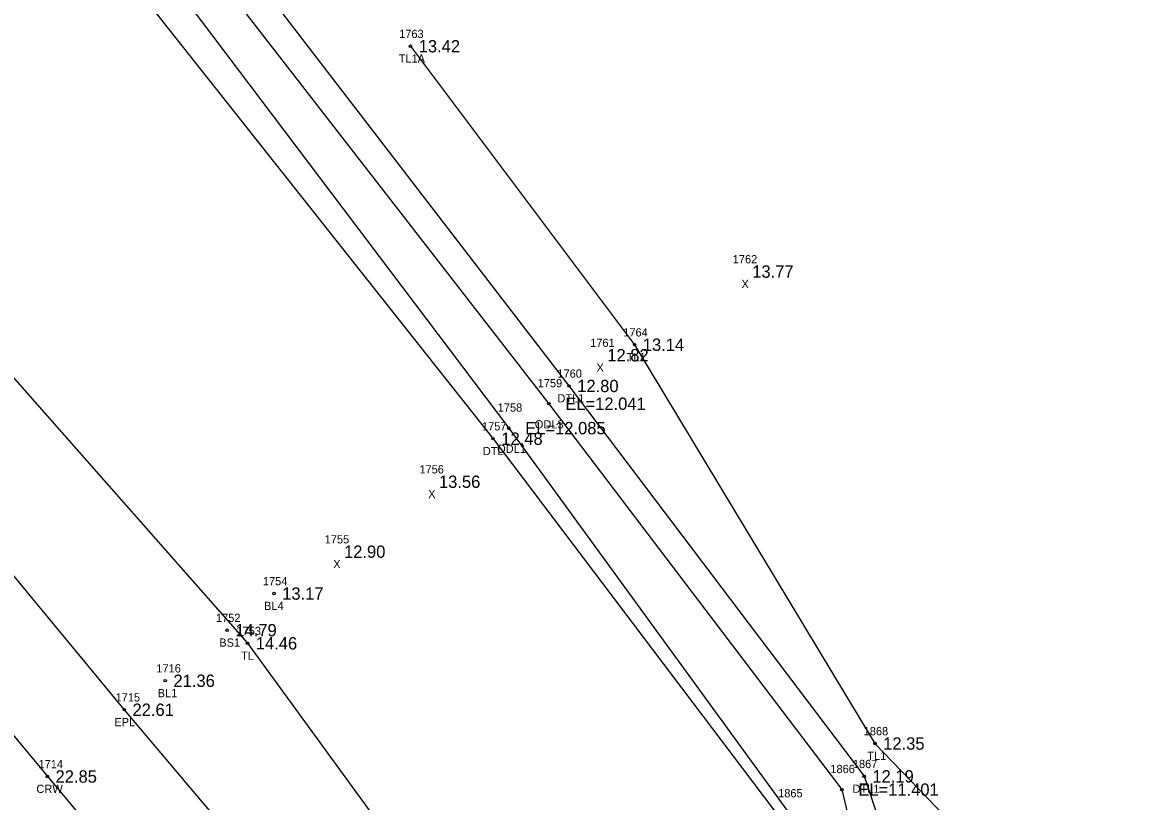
# Model space of a CAD drawing. Extents: x 2042117 to 2045853, y 303080 to 309569.
# Drawn here: x 2043937.2 to 2044074.2, y 305334.8 to 305429.3 of the extents above; entities that cross this region are included whole.
import ezdxf

# ---------------------------------------------------------------- set-up
doc = ezdxf.new("R2010")
doc.units = 0
for name, color, linetype in [('RD_DTM_BkLn_txCode', 7, 'Continuous'), ('RD_EX_H2O', 7, 'Continuous'), ('RD_EX_H2O_txCode', 7, 'Continuous'), ('RD_EX_Misc_txCode', 7, 'Continuous'), ('RD_EX_Road', 7, 'Continuous'), ('RD_EX_Road_txCode', 7, 'Continuous'), ('RD_EX_TX_H2O_ELEV', 7, 'Continuous'), ('RD_EX_TX_Misc_ELEV', 7, 'Continuous'), ('RD_EX_TX_Road_ELEV', 7, 'Continuous'), ('RD_EX_TX_VEG_ELEV', 7, 'Continuous'), ('RD_EX_VEG', 7, 'Continuous'), ('RD_EX_VEG_txCode', 7, 'Continuous'), ('RD_HC_Cl', 7, 'Continuous'), ('RD_HC_Survey_ELEV', 7, 'Continuous'), ('RD_HC_Survey_txCode', 7, 'Continuous'), ('RD_SMD_Locator', 7, 'Continuous')]:
    doc.layers.add(name, color=color, linetype=linetype)

msp = doc.modelspace()

# ---------------------------------------------------------------- linework, layer by layer
at = {"layer": 'RD_EX_H2O'}
for points in [[(2043695.41, 305785.95), (2043753.23, 305702.74), (2043816.84, 305621.67), (2043878.98, 305542.47), (2043936.42, 305466.41), (2044001.08, 305383.06), (2044036.64, 305336.24), (2044042.32, 305312.25), (2044044.08, 305296.68), (2044037.04, 305284.58), (2044037.23, 305281.89), (2044040.11, 305279.62), (2044044.74, 305276.06), (2044050.89, 305261.28), (2044092.5, 305206.78), (2044153.45, 305129.2), (2044155.72, 305128.46), (2044158.75, 305129.8), (2044171.64, 305145.93), (2044183.17, 305157.87), (2044199.16, 305188.17), (2044208.66, 305215.31)], [(2043691.65, 305782.08), (2043750.76, 305701.1), (2043812.59, 305619.17), (2043875.5, 305539.19), (2043933.11, 305463.61), (2043996.22, 305380.1), (2044030.28, 305333.3), (2044036.73, 305312.37), (2044037.31, 305297.73), (2044030.81, 305285.38), (2044029.9, 305283.95), (2044027.87, 305283.16)], [(2043688.94, 305780.02), (2043748.1, 305697.94), (2043809.2, 305616.91), (2043872.33, 305536.25), (2043929.28, 305460.89), (2043994.32, 305378.82), (2044029.48, 305332.31), (2044031.68, 305311), (2044031.99, 305298.04), (2044028.8, 305286.25)], [(2043939.38, 305468.62), (2044003.53, 305385.22), (2044039.35, 305337.85), (2044047.71, 305312.67), (2044046.57, 305295.78), (2044040.04, 305284.22), (2044040.55, 305281.91), (2044045.48, 305279.05), (2044047.12, 305275.75), (2044052.64, 305262.28), (2044093.07, 305207.37)]]:
    msp.add_lwpolyline(points, dxfattribs=at)
at = {"layer": 'RD_EX_Road'}
msp.add_lwpolyline([(2043821.87, 305499.1), (2043885.81, 305423.07), (2043949.56, 305345.93), (2044013.41, 305270.34), (2044077.97, 305194.15), (2044141.4, 305117.67), (2044205.92, 305040.83), (2044269.54, 304964.65), (2044331.73, 304891.04), (2044335.22, 304889.2), (2044346.01, 304875.31), (2044356.18, 304867.61), (2044370.01, 304868.14), (2044386.83, 304866.36), (2044389.44, 304849.53), (2044390.71, 304830.73), (2044393.77, 304818.44), (2044395.5, 304814.18), (2044398.16, 304811.09)], dxfattribs=at)
at = {"layer": 'RD_EX_VEG'}
for points in [[(2043547.51, 305881.5), (2043539.7, 305861.32), (2043541.74, 305855.07), (2043567.73, 305828.7), (2043642.4, 305738.29), (2043706.88, 305661.84), (2043768.33, 305586.86), (2043834.29, 305506.38), (2043895.63, 305432.16), (2043964.52, 305353.99), (2044012.41, 305288.23), (2044020.96, 305286.08), (2044026.64, 305287.13), (2044039.88, 305282.36)], [(2043984.29, 305426.44), (2044011.49, 305390.22), (2044040.66, 305341.83), (2044056.64, 305325.24), (2044053.79, 305304.43), (2044049.07, 305293.73), (2044039.88, 305282.36)]]:
    msp.add_lwpolyline(points, dxfattribs=at)
at = {"layer": 'RD_HC_Cl'}
msp.add_line((2043284.3, 306123.24), (2045221.31, 303804), dxfattribs=at)
at = {"layer": 'RD_SMD_Locator'}
for centre in [(2043984.29, 305426.44), (2044011.49, 305390.22), (2044003.53, 305385.22), (2044001.08, 305383.06), (2043994.32, 305378.82), (2043996.22, 305380.1), (2043967.73, 305360.03), (2043962.04, 305355.58), (2043964.52, 305353.99), (2043954.53, 305349.45), (2043949.56, 305345.93), (2044040.66, 305341.83), (2043940.22, 305337.83), (2044039.35, 305337.85), (2044036.64, 305336.24)]:
    msp.add_circle(centre, 0.15, dxfattribs=at)

# ---------------------------------------------------------------- texts
at = {"layer": 'RD_DTM_BkLn_txCode'}
for s, p in [('1754', (2043966.38, 305361.03)), ('BL4', (2043966.52, 305358.03)), ('1752', (2043960.69, 305356.58)), ('BS1', (2043961.09, 305353.58)), ('1716', (2043953.45, 305350.45)), ('BL1', (2043953.61, 305347.45))]:
    msp.add_text(s, height=1, dxfattribs=at).set_placement(p)
at = {"layer": 'RD_EX_H2O_txCode'}
for s, p in [('1760', (2044002.12, 305386.22)), ('1759', (2043999.73, 305385.06)), ('1758', (2043994.88, 305382.1)), ('DTL1', (2044002.12, 305383.22)), ('1757', (2043992.97, 305379.82)), ('ODL3', (2043999.38, 305380.06)), ('DTL', (2043993.07, 305376.82)), ('ODL1', (2043994.81, 305377.1)), ('1866', (2044035.25, 305338.24)), ('1867', (2044037.98, 305338.85)), ('DTL1', (2044037.94, 305335.85)), ('1865', (2044028.91, 305335.3))]:
    msp.add_text(s, height=1, dxfattribs=at).set_placement(p)
at = {"layer": 'RD_EX_Misc_txCode'}
for s, p in [('1762', (2044023.4, 305400.1)), ('X', (2044024.46, 305397.1)), ('1761', (2044006.1, 305389.95)), ('X', (2044006.87, 305386.95)), ('1756', (2043985.38, 305374.6)), ('X', (2043986.44, 305371.6)), ('1755', (2043973.88, 305366.11)), ('X', (2043974.92, 305363.11))]:
    msp.add_text(s, height=1, dxfattribs=at).set_placement(p)
at = {"layer": 'RD_EX_Road_txCode'}
for s, p in [('1715', (2043948.5, 305346.93)), ('EPL', (2043948.35, 305343.93))]:
    msp.add_text(s, height=1, dxfattribs=at).set_placement(p)
at = {"layer": 'RD_EX_TX_H2O_ELEV'}
for s, p in [('12.80', (2044004.53, 305384.47)), ('EL=12.041', (2044003.08, 305382.31)), ('EL=12.085', (2043998.22, 305379.35)), ('12.48', (2043995.32, 305378.07)), ('12.19', (2044040.35, 305337.1)), ('EL=11.401', (2044038.64, 305335.49))]:
    msp.add_text(s, height=1.5, dxfattribs=at).set_placement(p)
at = {"layer": 'RD_EX_TX_Misc_ELEV'}
for s, p in [('13.77', (2044025.77, 305398.35)), ('12.82', (2044008.18, 305388.2)), ('13.56', (2043987.75, 305372.85)), ('12.90', (2043976.23, 305364.36)), ('13.17', (2043968.73, 305359.28)), ('14.79', (2043963.04, 305354.83)), ('21.36', (2043955.53, 305348.7))]:
    msp.add_text(s, height=1.5, dxfattribs=at).set_placement(p)
at = {"layer": 'RD_EX_TX_Road_ELEV'}
msp.add_text('22.61', height=1.5, dxfattribs=at).set_placement((2043950.56, 305345.18))
at = {"layer": 'RD_EX_TX_VEG_ELEV'}
for s, p in [('13.42', (2043985.29, 305425.69)), ('13.14', (2044012.49, 305389.47)), ('14.46', (2043965.52, 305353.24)), ('12.35', (2044041.66, 305341.08))]:
    msp.add_text(s, height=1.5, dxfattribs=at).set_placement(p)
at = {"layer": 'RD_EX_VEG_txCode'}
for s, p in [('1763', (2043982.92, 305427.44)), ('TL1A', (2043982.86, 305424.44)), ('1764', (2044010.12, 305391.22)), ('TL1', (2044010.55, 305388.22)), ('1753', (2043963.17, 305354.99)), ('TL', (2043963.74, 305351.99)), ('1868', (2044039.29, 305342.83)), ('TL1', (2044039.73, 305339.83))]:
    msp.add_text(s, height=1, dxfattribs=at).set_placement(p)
at = {"layer": 'RD_HC_Survey_ELEV'}
msp.add_text('22.85', height=1.5, dxfattribs=at).set_placement((2043941.22, 305337.08))
at = {"layer": 'RD_HC_Survey_txCode'}
for s, p in [('1714', (2043939.15, 305338.83)), ('CRW', (2043938.9, 305335.83))]:
    msp.add_text(s, height=1, dxfattribs=at).set_placement(p)

doc.saveas('drawing.dxf')
